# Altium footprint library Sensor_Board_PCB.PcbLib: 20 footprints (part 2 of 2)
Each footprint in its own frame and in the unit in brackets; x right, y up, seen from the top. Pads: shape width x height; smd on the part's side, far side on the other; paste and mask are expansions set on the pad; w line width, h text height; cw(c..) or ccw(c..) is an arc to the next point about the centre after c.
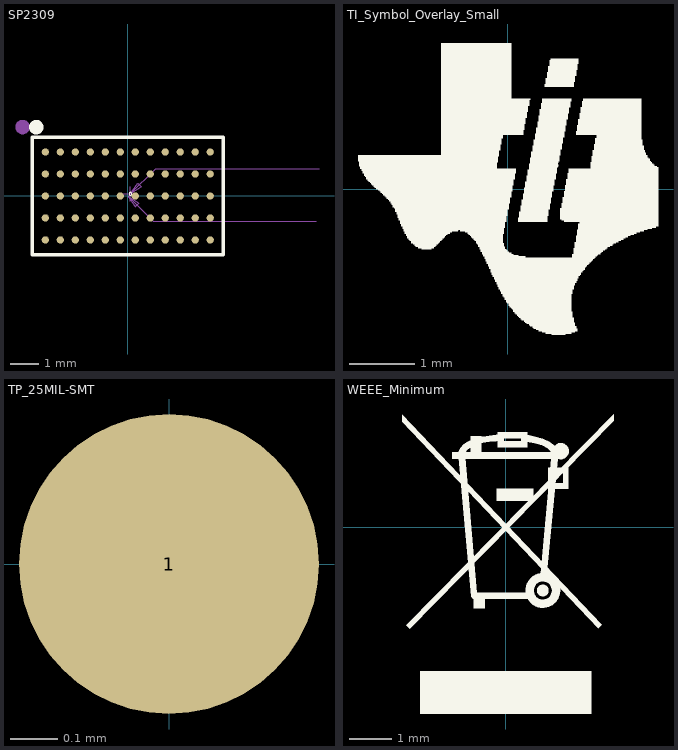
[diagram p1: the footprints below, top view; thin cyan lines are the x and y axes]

## SP2309 [mil] "SP2309"
pads (60):
  round 10 smd: A1(-113.7,60.63) A2(-93.03,60.63) A3(-72.36,60.63) A4(-51.69,60.63) A5(-31.02,60.63) A6(-10.35,60.63) A7(10.31,60.63) A8(30.98,60.63) A9(51.65,60.63) A10(72.32,60.63) A11(92.99,60.63) A12(113.66,60.63) B1(-113.7,30.31) B2(-93.03,30.31) B3(-72.36,30.31) B4(-51.69,30.31) B5(-31.02,30.31) B6(-10.35,30.31) B7(10.31,30.31) B8(30.98,30.31) B9(51.65,30.31) B10(72.32,30.31) B11(92.99,30.31) B12(113.66,30.31) C1(-113.7,0) C2(-93.03,0) C3(-72.36,0) C4(-51.69,0) C5(-31.02,0) C6(-10.35,0) C7(10.31,0) C8(30.98,0) C9(51.65,0) C10(72.32,0) C11(92.99,0) C12(113.66,0) D1(-113.7,-30.31) D2(-93.03,-30.31) D3(-72.36,-30.31) D4(-51.69,-30.31) D5(-31.02,-30.31) D6(-10.35,-30.31) D7(10.31,-30.31) D8(30.98,-30.31) D9(51.65,-30.31) D10(72.32,-30.31) D11(92.99,-30.31) D12(113.66,-30.31) E1(-113.7,-60.63) E2(-93.03,-60.63) E3(-72.36,-60.63) E4(-51.69,-60.63) E5(-31.02,-60.63) E6(-10.35,-60.63) E7(10.31,-60.63) E8(30.98,-60.63) E9(51.65,-60.63) E10(72.32,-60.63) E11(92.99,-60.63) E12(113.66,-60.63)
Top Overlay:
  circle w10: c-126.17,94.78 r5
  circle w1: c3.7,2.77 r2
  lines w1: -131.5,-80.91 -131.5,80.91 ; -131.5,-80.91 131.5,-80.91 ; -131.5,-80.91 131.5,-80.91 ; -131.5,-80.91 -131.5,80.91 ; -131.5,80.91 131.5,80.91 131.5,-80.91
  lines w5: -131.5,80.91 131.5,80.91 ; -131.5,80.91 -131.5,-80.91 131.5,-80.91 ; -131.5,80.91 131.5,80.91 ; 131.5,-80.91 131.5,80.91 ; 131.5,-80.91 131.5,80.91
  text ".Designator" at -109.8,94.67 h25
Mechanical 5:
  circle w10: c-145,95.01 r5
  lines w1: -6.14,2.77 13.54,2.77 ; 3.7,-7.07 3.7,12.61 ; 260,-35 35,-35 0,0 ; 263.7,37.77 38.7,37.77 3.7,2.77 ; -131.5,-80.91 131.5,-80.91 ; -131.5,-80.91 -131.5,80.91 ; -131.5,-80.91 -131.5,80.91 ; -131.5,-80.91 131.5,-80.91 ; -131.5,80.91 131.5,80.91 ; -131.5,80.91 131.5,80.91 ; 0,0 10,-15 15,-10 0,0 ; 3.7,2.77 13.7,17.77 18.7,12.77 3.7,2.77 ; 131.5,-80.91 131.5,80.91 ; 131.5,-80.91 131.5,80.91
  text "Array Center(109um,80um)" at 131.91,41.95 h8
  text "Center of BGA(Die)" at 137.5,-27.67 h8
  text "Center of the package(0,0)" at 137,-47.67 h8
Mechanical 16:
  lines w1: -131.5,-80.91 131.5,-80.91 131.5,80.91 -131.5,80.91 -131.5,-80.91
  text "A12" at 104.06,60.63 h8
  text "B1" at -120.1,30.31 h8
  text "C1" at -120.1,0 h8
  text "C12" at 104.06,0 h8
  text "E5" at -37.42,-60.63 h8
  text "A1" at -120.1,60.63 h8
  text "E6" at -16.75,-60.63 h8
  text "E8" at 24.58,-60.63 h8
  text "E7" at 3.91,-60.63 h8
  text "A8" at 24.58,60.63 h8
  text "C3" at -78.76,0 h8
  text "C8" at 24.58,0 h8
  text "A5" at -37.42,60.63 h8
  text "B8" at 24.58,30.31 h8
  text "C9" at 45.25,0 h8
  text "C2" at -99.43,0 h8
  text "B2" at -99.43,30.31 h8
  text "C7" at 3.91,0 h8
  text "B3" at -78.76,30.31 h8
  text "B11" at 83.39,30.31 h8
  text "E2" at -99.43,-60.63 h8
  text "E1" at -120.1,-60.63 h8
  text "C11" at 83.39,0 h8
  text "E12" at 104.06,-60.63 h8
  text "C4" at -58.09,0 h8
  text "B5" at -37.42,30.31 h8
  text "B4" at -58.09,30.31 h8
  text "C10" at 62.72,0 h8
  text "E11" at 83.39,-60.63 h8
  text "E3" at -78.76,-60.63 h8
  text "E4" at -58.09,-60.63 h8
  text "D10" at 62.72,-30.31 h8
  text "E10" at 62.72,-60.63 h8
  text "E9" at 45.25,-60.63 h8
  text "D12" at 104.06,-30.31 h8
  text "D11" at 83.39,-30.31 h8
  text "D1" at -120.1,-30.31 h8
  text "D2" at -99.43,-30.31 h8
  text "A7" at 3.91,60.63 h8
  text "A4" at -58.09,60.63 h8
  text "A11" at 83.39,60.63 h8
  text "B12" at 104.06,30.31 h8
  text "B10" at 62.72,30.31 h8
  text "A2" at -99.43,60.63 h8
  text "B9" at 45.25,30.31 h8
  text "B7" at 3.91,30.31 h8
  text "D9" at 45.25,-30.31 h8
  text "D8" at 24.58,-30.31 h8
  text "D7" at 3.91,-30.31 h8
  text "D6" at -16.75,-30.31 h8
  text "D5" at -37.42,-30.31 h8
  text "D4" at -58.09,-30.31 h8
  text "D3" at -78.76,-30.31 h8
  text "A3" at -78.76,60.63 h8
  text "A10" at 62.72,60.63 h8
  text "A9" at 45.25,60.63 h8
  text "C5" at -37.42,0 h8
  text "B6" at -16.75,30.31 h8
  text "A6" at -16.75,60.63 h8
  text "C6" at -16.75,0 h8

## TI_Symbol_Overlay_Small [mil]
Top Overlay:
  drawing of 3 lines, arcs and shapes, not listed

## TP_25MIL-SMT [mil]
pads (1):
  round 25 smd mask-2.5: 1(0,0)

## WEEE_Minimum [mil] "WEEElie bin"
height 157.48
Top Overlay:
  drawing of 23 lines, arcs and shapes, not listed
